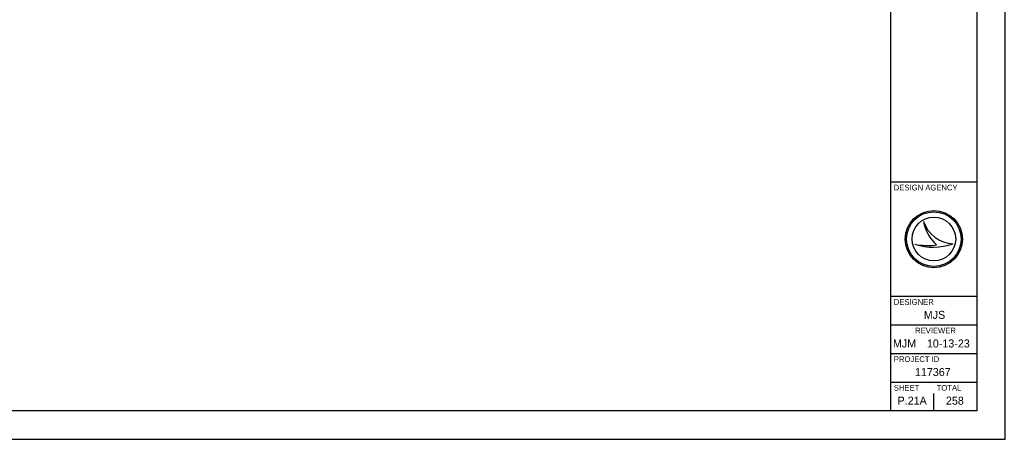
# Model space of a CAD drawing. Extents: x 0 to 34, y 0 to 22.
# Drawn here: x 16.76 to 34, y 0 to 7.33 of the extents above; entities that cross this region are included whole.
import ezdxf

# ---------------------------------------------------------------- set-up
doc = ezdxf.new("R2010")
doc.units = 0
for name, color, linetype in [('SH_Border', 7, 'Continuous'), ('SH_Cut_Line', 7, 'Continuous'), ('SH_Data', 7, 'Continuous')]:
    doc.layers.add(name, color=color, linetype=linetype)

msp = doc.modelspace()

# ---------------------------------------------------------------- linework, layer by layer
at = {"layer": 'SH_Border'}
for p, q in [((32, 0.5), (32, 21.5)), ((32, 4.5), (33.5, 4.5)), ((32, 2.5), (33.5, 2.5)), ((32, 2), (33.5, 2)), ((32, 1.5), (33.5, 1.5)), ((32, 1), (33.5, 1))]:
    msp.add_line(p, q, dxfattribs=at)
msp.add_lwpolyline([(1.5, 21.5), (33.5, 21.5), (33.5, 0.5), (1.5, 0.5)], close=True, dxfattribs=at)
at = {"layer": 'SH_Cut_Line'}
msp.add_lwpolyline([(0, 0), (34, 0), (34, 22), (0, 22)], close=True, dxfattribs=at)
at = {"layer": 'SH_Data'}
for p, q in [((32.567, 3.81), (32.567, 3.81)), ((32.75, 3.5), (32.75, 3.5)), ((32.417, 3.41), (32.417, 3.41)), ((33.087, 3.419), (33.087, 3.419)), ((32.75, 0.5), (32.75, 0.8)), ((32.375, 0.675), (32.375, 0.675))]:
    msp.add_line(p, q, dxfattribs=at)
for radius in [0.5, 0.477, 0.477, 0.382]:
    msp.add_circle((32.75, 3.5), radius, dxfattribs=at)
for centre, radius, start, end in [((33.116, 3.998), 0.58, 198.9257, 198.9319), ((33.347, 3.97), 0.796, 191.6379, 191.6421), ((33.116, 3.998), 0.58, 198.9319, 267.1657), ((33.347, 3.97), 0.796, 191.6421, 226.0947), ((32.739, 4.37), 1.013, 251.4576, 290.0832), ((32.648, 4.654), 1.266, 259.4964, 259.4995), ((32.739, 4.37), 1.013, 251.4527, 251.4576), ((32.648, 4.654), 1.266, 259.4995, 276.6672)]:
    msp.add_arc(centre, radius, start, end, dxfattribs=at)

# ---------------------------------------------------------------- texts
for s, height, p in [('DESIGN AGENCY', 0.1, (32.05, 4.35)), ('DESIGNER', 0.1, (32.05, 2.35)), ('MJS', 0.14, (32.574, 2.105)), ('REVIEWER', 0.1, (32.422, 1.85)), ('MJM', 0.14, (32.035, 1.605)), ('10-13-23', 0.14, (32.629, 1.605)), ('PROJECT ID', 0.1, (32.05, 1.35)), ('117367', 0.14, (32.42, 1.105)), ('SHEET', 0.1, (32.05, 0.85)), ('TOTAL', 0.1, (32.8, 0.85)), ('P.21A', 0.14, (32.116, 0.605)), ('258', 0.14, (32.962, 0.605))]:
    msp.add_text(s, height=height, dxfattribs=at).set_placement(p)

doc.saveas('drawing.dxf')
